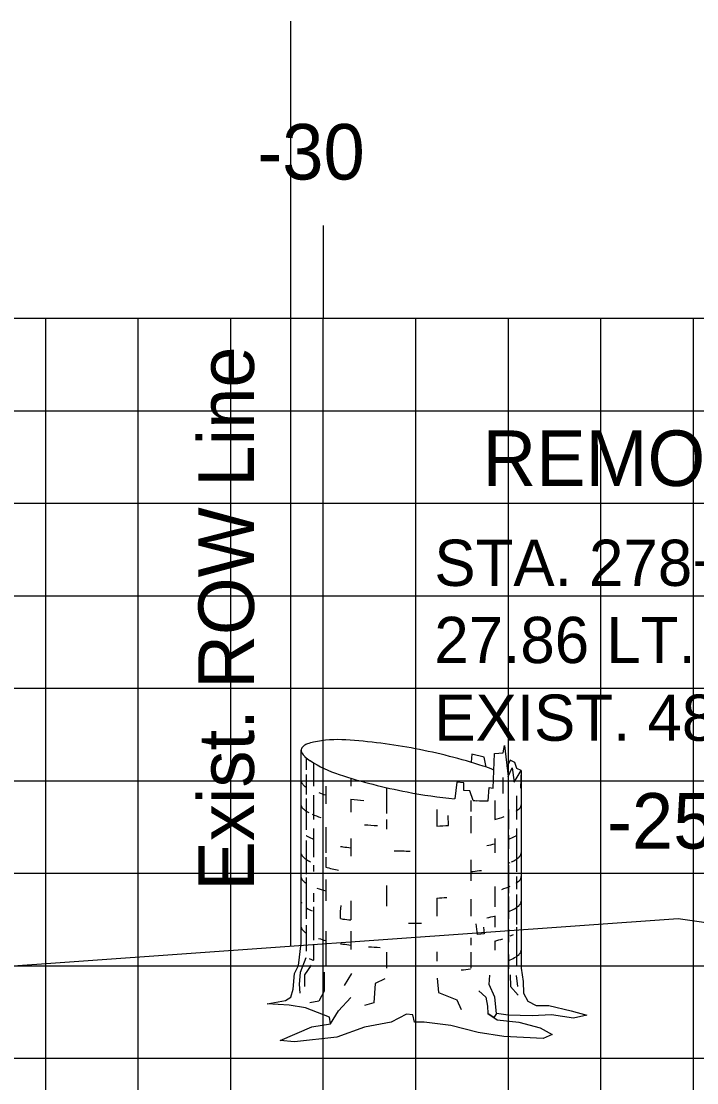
# Model space of a CAD drawing. Extents: x 854676 to 854846, y 366268 to 366378.
# Drawn here: x 854725.84 to 854733.14, y 366308.97 to 366320.45 of the extents above; entities that cross this region are included whole.
import ezdxf

# ---------------------------------------------------------------- set-up
doc = ezdxf.new("R2010")
doc.units = 0
for name, color, linetype in [('ANNOTATION', 7, 'Continuous'), ('D_Text_Monospaced', 7, 'Continuous'), ('D_Text_Standard', 7, 'Continuous'), ('E_ROW_Line', 7, 'Continuous'), ('H_V ANNOTATION', 7, 'Continuous'), ('MAJOR', 7, 'Continuous'), ('MINOR', 7, 'Continuous'), ('S_Roadway_Centerline', 7, 'Continuous'), ('S_Trees_Decid_Pay', 7, 'Continuous')]:
    doc.layers.add(name, color=color, linetype=linetype)

msp = doc.modelspace()

# ---------------------------------------------------------------- linework, layer by layer
at = {"layer": 'E_ROW_Line'}
msp.add_line((854728.757, 366310.447), (854728.757, 366320.447), dxfattribs=at)
at = {"layer": 'MAJOR'}
for p, q in [((854729.106, 366318.238), (854729.106, 366317.236)), ((854689.106, 366317.236), (854829.106, 366317.236)), ((854689.106, 366317.236), (854829.106, 366317.236)), ((854729.106, 366302.236), (854729.106, 366317.236)), ((854689.106, 366312.236), (854829.106, 366312.236))]:
    msp.add_line(p, q, dxfattribs=at)
at = {"layer": 'MINOR'}
for p, q in [((854726.106, 366302.236), (854726.106, 366317.236)), ((854727.106, 366302.236), (854727.106, 366317.236)), ((854728.106, 366302.236), (854728.106, 366317.236)), ((854730.106, 366302.236), (854730.106, 366317.236)), ((854731.106, 366302.236), (854731.106, 366317.236)), ((854732.106, 366302.236), (854732.106, 366317.236)), ((854733.106, 366302.236), (854733.106, 366317.236)), ((854689.106, 366316.236), (854829.106, 366316.236)), ((854689.106, 366315.236), (854829.106, 366315.236)), ((854689.106, 366314.236), (854829.106, 366314.236)), ((854689.106, 366313.236), (854829.106, 366313.236)), ((854689.106, 366311.236), (854829.106, 366311.236)), ((854689.106, 366310.236), (854829.106, 366310.236)), ((854689.106, 366309.236), (854829.106, 366309.236))]:
    msp.add_line(p, q, dxfattribs=at)
at = {"layer": 'S_Roadway_Centerline'}
msp.add_lwpolyline([(854702.478, 366309.069), (854721.133, 366310.121), (854725.449, 366310.212), (854732.94, 366310.746), (854735.545, 366310.37), (854737.315, 366310.547), (854738.261, 366310.513), (854740.788, 366310.363), (854741.663, 366310.048), (854741.948, 366309.957), (854743.884, 366310.025), (854748.429, 366310.204), (854751.474, 366310.169), (854759.551, 366310.169), (854768.432, 366309.965), (854771.526, 366309.892)], dxfattribs=at)
at = {"layer": 'S_Trees_Decid_Pay'}
for p, q in [((854728.92, 366312.475), (854728.92, 366312.354)), ((854729, 366312.43), (854729, 366312.177)), ((854728.92, 366312.302), (854728.92, 366312.088)), ((854729.405, 366312.263), (854729.405, 366312.177)), ((854731.045, 366312.271), (854731.045, 366312.097)), ((854729.133, 366312.177), (854729.133, 366311.985)), ((854729.788, 366312.162), (854729.788, 366311.882)), ((854728.92, 366312.043), (854728.92, 366311.705)), ((854729, 366312.08), (854729, 366311.816)), ((854729.405, 366312.036), (854729.405, 366311.896)), ((854730.699, 366312.024), (854730.699, 366311.905)), ((854730.96, 366312.022), (854730.96, 366311.818)), ((854731.194, 366312.071), (854731.194, 366311.816)), ((854730.334, 366311.925), (854730.334, 366311.746)), ((854731.108, 366311.925), (854731.108, 366311.713)), ((854729.788, 366311.816), (854729.788, 366311.713)), ((854730.461, 366311.753), (854730.456, 366311.86)), ((854730.699, 366311.853), (854730.699, 366311.668)), ((854729, 366311.719), (854729, 366311.411)), ((854729.133, 366311.734), (854729.133, 366311.456)), ((854731.108, 366311.648), (854731.108, 366311.5)), ((854731.194, 366311.719), (854731.194, 366311.25)), ((854728.92, 366311.588), (854728.92, 366311.227)), ((854729.405, 366311.61), (854729.405, 366311.419)), ((854730.96, 366311.61), (854730.96, 366311.456)), ((854729.133, 366311.411), (854729.133, 366311.302)), ((854729, 366311.322), (854729, 366311.256)), ((854730.699, 366311.382), (854730.699, 366311.154)), ((854731.108, 366311.322), (854731.108, 366311.022)), ((854728.92, 366311.19), (854728.92, 366310.742)), ((854731.194, 366311.199), (854731.194, 366311.065)), ((854729.133, 366311.167), (854729.133, 366310.939)), ((854729.788, 366311.102), (854729.788, 366310.881)), ((854730.96, 366311.093), (854730.96, 366310.874)), ((854729, 366311.022), (854729, 366310.925)), ((854730.334, 366310.967), (854730.334, 366310.771)), ((854730.699, 366310.956), (854730.699, 366310.771)), ((854731.108, 366310.984), (854731.108, 366310.742)), ((854731.194, 366311.007), (854731.194, 366310.682)), ((854729, 366310.874), (854729, 366310.513)), ((854729.405, 366310.939), (854729.405, 366310.731)), ((854730.96, 366310.774), (854730.96, 366310.653)), ((854728.92, 366310.676), (854728.92, 366310.394)), ((854729.133, 366310.61), (854729.133, 366310.227)), ((854729.405, 366310.61), (854729.405, 366310.41)), ((854731.108, 366310.631), (854731.108, 366310.49)), ((854731.194, 366310.653), (854731.194, 366310.233)), ((854730.699, 366310.536), (854730.699, 366310.459)), ((854730.96, 366310.502), (854730.96, 366310.404)), ((854729, 366310.461), (854729, 366310.295)), ((854729.788, 366310.381), (854729.788, 366310.208)), ((854730.334, 366310.387), (854730.334, 366310.284)), ((854730.699, 366310.381), (854730.699, 366310.208)), ((854731.108, 366310.358), (854731.108, 366310.202)), ((854729.41, 366310.153), (854729.33, 366310.021)), ((854731.191, 366310.13), (854731.206, 366310.013))]:
    msp.add_line(p, q, dxfattribs=at)
for points in [[(854731.245, 366312.345), (854731.245, 366310.208), (854731.265, 366310.066), (854731.271, 366309.94), (854731.315, 366309.854), (854731.407, 366309.805), (854731.543, 366309.805), (854731.786, 366309.749), (854731.953, 366309.7), (854731.811, 366309.669), (854731.574, 366309.706), (854731.364, 366309.694), (854731.103, 366309.7), (854730.979, 366309.718), (854730.948, 366309.675), (854730.886, 366309.718), (854730.985, 366309.65), (854731.22, 366309.625), (854731.45, 366309.564), (854731.58, 366309.494), (854731.481, 366309.45), (854731.059, 366309.469), (854730.781, 366309.513), (854730.483, 366309.589), (854730.196, 366309.625), (854730.091, 366309.625), (854730.073, 366309.706), (854730.005, 366309.712), (854729.838, 366309.625), (854729.552, 366309.57), (854729.254, 366309.463), (854728.794, 366309.414), (854728.64, 366309.426), (854728.982, 366309.576), (854729.185, 366309.607), (854729.173, 366309.681), (854728.914, 366309.78), (854728.738, 366309.811), (854728.498, 366309.823), (854728.696, 366309.86), (854728.757, 366309.897), (854728.782, 366309.984), (854728.794, 366310.153), (854728.839, 366310.239), (854728.868, 366310.48), (854728.868, 366312.566)], [(854730.889, 366312.018), (854730.897, 366312.162), (854730.942, 366312.154), (854730.956, 366312.529), (854731.051, 366312.537), (854731.065, 366312.617), (854731.103, 366312.28), (854731.148, 366312.374), (854731.168, 366312.22), (854731.245, 366312.345), (854731.239, 366312.156)], [(854730.866, 366312.384), (854730.845, 366312.492), (854730.713, 366312.522), (854730.706, 366312.435)], [(854731.245, 366312.345), (854731.199, 366312.368), (854731.177, 366312.434), (854731.125, 366312.457), (854731.091, 366312.382)], [(854730.727, 366312.022), (854730.691, 366312.125), (854730.625, 366312.131), (854730.625, 366312.213), (854730.551, 366312.22), (854730.526, 366312.04)], [(854729.292, 366310.745), (854729.293, 366310.822), (854729.301, 366310.888)], [(854730.837, 366310.653), (854730.845, 366310.579), (854730.771, 366310.573), (854730.757, 366310.69)], [(854728.918, 366310.322), (854728.858, 366310.161), (854728.844, 366310.036), (854728.852, 366309.938)], [(854728.975, 366310.241), (854728.904, 366310.138), (854728.904, 366310.013)], [(854729.116, 366310.167), (854729.116, 366309.961), (854729.058, 366309.852), (854728.961, 366309.835)], [(854729.771, 366310.093), (854729.668, 366310.042), (854729.653, 366309.835), (854729.55, 366309.807)], [(854730.336, 366310.101), (854730.353, 366309.947), (854730.551, 366309.866), (854730.596, 366309.763)], [(854730.979, 366309.718), (854730.96, 366309.897), (854730.899, 366310.034), (854730.905, 366310.134)], [(854731.125, 366310.138), (854731.131, 366310.013), (854731.213, 366309.918)], [(854730.788, 366309.965), (854730.862, 366309.897), (854730.88, 366309.799), (854730.886, 366309.718)], [(854729.185, 366309.607), (854729.272, 366309.749), (854729.404, 366309.891)]]:
    msp.add_lwpolyline(points, dxfattribs=at)
for centre, radius, start, end in [((854729.266, 366311.381), 1.299, 86.3056, 101.7221), ((854728.955, 366306.564), 6.126, 79.2221, 86.3056), ((854728.914, 366312.566), 0.0467, 157.54, 169.2221), ((854728.914, 366312.566), 0.0467, 169.2221, 180.9043), ((854728.922, 366312.566), 0.0544, 180.9043, 191.7221), ((854728.921, 366312.563), 0.0544, 146.7221, 157.54), ((854728.93, 366312.557), 0.0645, 134.0453, 146.7221), ((854728.96, 366312.527), 0.107, 124.2221, 134.0453), ((854728.991, 366312.48), 0.164, 110.0157, 124.2221), ((854729.099, 366312.183), 0.48, 101.7221, 110.0157), ((854728.955, 366306.564), 6.126, 72.1387, 79.2221), ((854728.932, 366312.568), 0.0645, 191.7221, 204.3989), ((854728.971, 366312.586), 0.107, 204.3989, 214.2221), ((854729.018, 366312.618), 0.164, 214.2221, 228.4286), ((854729.227, 366312.854), 0.48, 228.4286, 236.7221), ((854729.677, 366313.539), 1.299, 236.7221, 252.1387), ((854730.435, 366311.158), 1.299, 66.6931, 72.1387), ((854728.922, 366312.239), 0.0554, 191.6815, 202.5), ((854728.931, 366312.243), 0.0657, 202.5, 215.1737), ((854731.157, 366318.133), 6.126, 252.1387, 259.2221), ((854728.967, 366312.268), 0.109, 215.1737, 225), ((854729.007, 366312.309), 0.166, 225, 238.33), ((854729.479, 366313.328), 1.292, 250.9084, 254.4349), ((854731.157, 366318.133), 6.126, 259.2221, 264.0853), ((854730.055, 366317.916), 5.916, 263.6913, 265.0485), ((854731.157, 366318.133), 6.126, 265.9754, 266.3056), ((854730.846, 366313.317), 1.299, 266.3056, 271.8711), ((854728.923, 366311.979), 0.0554, 191.6815, 202.5), ((854728.932, 366311.982), 0.0657, 202.5, 215.1737), ((854728.968, 366312.007), 0.109, 215.1737, 225), ((854729.008, 366312.048), 0.166, 225, 239.1924), ((854729.171, 366312.321), 0.484, 239.1924, 242.5838), ((854729.48, 366313.067), 1.292, 247.5, 251.9171), ((854731.104, 366312.048), 0.166, 300.8076, 315), ((854731.144, 366312.007), 0.109, 315, 324.8263), ((854731.18, 366311.982), 0.0657, 324.8263, 337.5), ((854731.189, 366311.979), 0.0554, 337.5, 348.3185), ((854731.197, 366311.977), 0.0476, 348.3185, 0), ((854730.056, 366317.655), 5.916, 265.1076, 266.4618), ((854730.056, 366317.655), 5.916, 272.6957, 273.9224), ((854730.632, 366313.067), 1.292, 284.7144, 289.3881), ((854729.008, 366311.785), 0.166, 238.3999, 239.1924), ((854729.171, 366312.057), 0.484, 239.1924, 247.5), ((854730.941, 366312.057), 0.484, 292.5, 300.8076), ((854731.104, 366311.785), 0.166, 300.8076, 302.9622), ((854729.48, 366312.804), 1.292, 247.5, 248.1929), ((854729.48, 366312.804), 1.292, 261.6338, 262.8454), ((854730.632, 366312.804), 1.292, 280.7368, 284.7144), ((854730.632, 366312.804), 1.292, 291.6463, 292.5), ((854728.923, 366311.458), 0.0554, 191.6815, 202.5), ((854728.932, 366311.462), 0.0657, 202.5, 215.1737), ((854728.968, 366311.487), 0.109, 215.1737, 225), ((854729.008, 366311.527), 0.166, 225, 239.1924), ((854730.056, 366317.392), 5.916, 262.8454, 263.6816), ((854730.056, 366317.392), 5.916, 268.2292, 269.8838), ((854731.104, 366311.527), 0.166, 300.8076, 315), ((854731.144, 366311.487), 0.109, 315, 324.8263), ((854731.18, 366311.462), 0.0657, 324.8263, 337.5), ((854731.189, 366311.458), 0.0554, 337.5, 348.3185), ((854731.197, 366311.456), 0.0476, 348.3185, 0), ((854729.171, 366311.8), 0.484, 239.1924, 245.3628), ((854729.48, 366312.546), 1.292, 254.3895, 260.7435), ((854730.632, 366312.546), 1.292, 291.5158, 292.5), ((854730.941, 366311.8), 0.484, 294.2275, 300.8076), ((854728.923, 366311.2), 0.0554, 191.6815, 202.5), ((854728.932, 366311.204), 0.0657, 202.5, 215.1737), ((854730.056, 366317.134), 5.916, 276.2405, 277.1546), ((854730.632, 366312.546), 1.292, 277.1546, 278.1274), ((854731.18, 366311.204), 0.0657, 324.8263, 337.5), ((854731.189, 366311.2), 0.0554, 337.5, 348.3185), ((854731.197, 366311.199), 0.0476, 348.3185, 0), ((854728.968, 366311.229), 0.109, 215.1737, 225), ((854729.008, 366311.27), 0.166, 225, 237.9306), ((854729.48, 366312.289), 1.292, 249.8999, 254.3895), ((854730.632, 366312.289), 1.292, 288.201, 292.5), ((854731.104, 366311.27), 0.166, 300.8076, 315), ((854731.144, 366311.229), 0.109, 315, 324.8263), ((854730.056, 366316.877), 5.916, 272.6957, 273.7279), ((854728.923, 366310.935), 0.0554, 191.6815, 202.5), ((854729.008, 366311.004), 0.166, 237.9306, 239.1924), ((854729.171, 366311.277), 0.484, 239.1924, 247.5), ((854730.941, 366311.277), 0.484, 292.5, 300.8076), ((854731.104, 366311.004), 0.166, 300.8076, 315), ((854731.144, 366310.964), 0.109, 315, 324.8263), ((854731.18, 366310.939), 0.0657, 324.8263, 337.5), ((854731.189, 366310.935), 0.0554, 337.5, 348.3185), ((854731.197, 366310.933), 0.0476, 348.3185, 0), ((854729.48, 366312.023), 1.292, 261.6205, 262.8454), ((854730.056, 366316.611), 5.916, 262.8454, 263.6816), ((854730.632, 366312.023), 1.292, 280.7537, 284.7144), ((854730.632, 366312.023), 1.292, 291.6463, 292.5), ((854728.923, 366310.663), 0.0554, 191.6815, 202.5), ((854728.932, 366310.667), 0.0657, 202.5, 215.1737), ((854728.968, 366310.692), 0.109, 215.1737, 225), ((854729.008, 366310.732), 0.166, 225, 237.9306), ((854730.056, 366316.611), 5.916, 269.7243, 270), ((854730.056, 366316.611), 5.916, 270, 271.0793), ((854729.48, 366311.752), 1.292, 250.8466, 254.3895), ((854730.632, 366311.752), 1.292, 284.7144, 288.6336), ((854730.941, 366311.005), 0.484, 292.5, 297.266), ((854729.48, 366311.752), 1.292, 261.6338, 262.8454), ((854730.056, 366316.34), 5.916, 262.8454, 263.6816), ((854730.056, 366316.34), 5.916, 265.539, 266.7363), ((854731.18, 366310.409), 0.0657, 324.8263, 337.5), ((854731.189, 366310.405), 0.0554, 337.5, 348.3185), ((854731.197, 366310.404), 0.0476, 348.3185, 0), ((854729.171, 366310.748), 0.484, 243.4501, 247.5), ((854729.471, 366311.498), 1.292, 247.9396, 248.6304), ((854730.632, 366311.494), 1.292, 291.6463, 292.5), ((854730.941, 366310.748), 0.484, 292.5, 300.8076), ((854731.104, 366310.475), 0.166, 300.8076, 315), ((854731.144, 366310.434), 0.109, 315, 324.8263), ((854730.056, 366316.082), 5.916, 275.2344, 276.2169)]:
    msp.add_arc(centre, radius, start, end, dxfattribs=at)

# ---------------------------------------------------------------- texts
at = {"layer": 'ANNOTATION'}
msp.add_text('REMOVE', height=0.6, dxfattribs=at).set_placement((854730.827, 366315.423))
at = {"layer": 'D_Text_Monospaced'}
for s, height, p in [('STA. 278+54.52', 0.49998, (854730.306, 366314.342)), ('27.86 LT.', 0.5, (854730.306, 366313.508)), ('EXIST. 48" ASH', 0.49998, (854730.306, 366312.668))]:
    msp.add_text(s, height=height, dxfattribs=at).set_placement(p)
at = {"layer": 'D_Text_Standard'}
msp.add_text("-25.0'", height=0.6, dxfattribs=at).set_placement((854732.174, 366311.502))
at = {"layer": 'E_ROW_Line'}
msp.add_text('Exist. ROW Line', height=0.6, rotation=90, dxfattribs=at).set_placement((854728.357, 366311.047))
at = {"layer": 'H_V ANNOTATION'}
msp.add_text('-30', height=0.6, dxfattribs=at).set_placement((854728.395, 366318.736))

doc.saveas('drawing.dxf')
